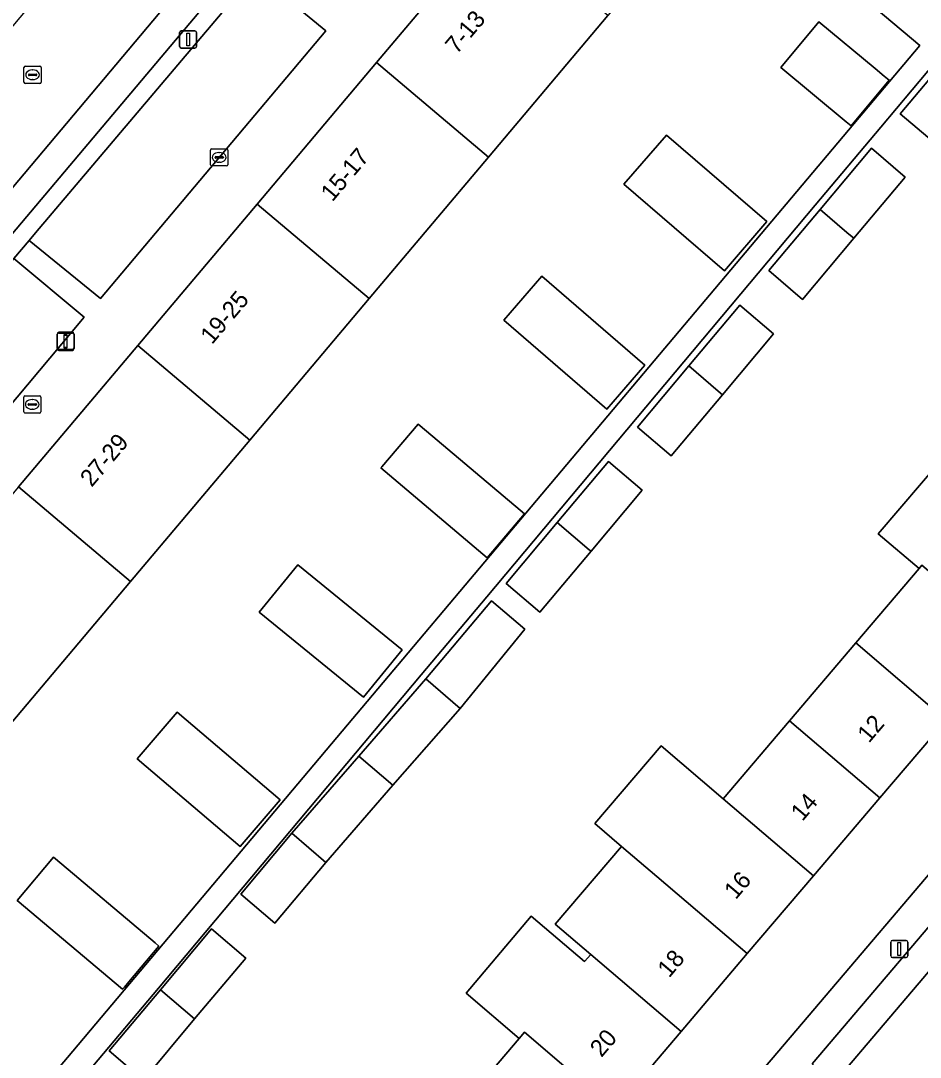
# Model space of a CAD drawing. Extents: x 162523 to 163266, y 381230 to 382050.
# Drawn here: x 163038.7 to 163090.9, y 381671.5 to 381731.7 of the extents above; entities that cross this region are included whole.
import ezdxf

# ---------------------------------------------------------------- set-up
doc = ezdxf.new("R2010")
doc.units = 0
for name, color, linetype in [('IMGEO_Brandkraan', 7, 'Continuous'), ('IMGEO_Erf', 7, 'Continuous'), ('IMGEO_Groenvoorziening', 7, 'Continuous'), ('IMGEO_Kolk', 7, 'Continuous'), ('IMGEO_Lichtmast', 7, 'Continuous'), ('IMGEO_Pand', 7, 'Continuous'), ('IMGEO_Pand_nummerreeks', 7, 'Continuous'), ('IMGEO_Parkeervlak_open', 7, 'Continuous'), ('IMGEO_Rijbaan_lokaal_open', 7, 'Continuous'), ('IMGEO_Rioolput', 7, 'Continuous'), ('IMGEO_Voetpad_open', 7, 'Continuous')]:
    doc.layers.add(name, color=color, linetype=linetype)

msp = doc.modelspace()

# ---------------------------------------------------------------- linework, layer by layer
at = {"layer": 'IMGEO_Brandkraan'}
for p, q in [((163038.839, 381709.011), (163038.839, 381709.863)), ((163038.914, 381709.937), (163039.766, 381709.937)), ((163039.84, 381709.863), (163039.84, 381709.011)), ((163039.098, 381709.431), (163039.098, 381709.443)), ((163039.536, 381709.394), (163039.138, 381709.394)), ((163039.141, 381709.48), (163039.539, 381709.48)), ((163039.327, 381709.717), (163039.352, 381709.717)), ((163039.582, 381709.443), (163039.582, 381709.431)), ((163039.766, 381708.937), (163038.914, 381708.937)), ((163039.35, 381709.157), (163039.325, 381709.157))]:
    msp.add_line(p, q, dxfattribs=at)
for points in [[(163038.839, 381709.011), (163038.839, 381709.863)], [(163038.914, 381709.937), (163039.766, 381709.937)], [(163039.84, 381709.863), (163039.84, 381709.011)], [(163039.766, 381708.937), (163038.914, 381708.937)]]:
    msp.add_lwpolyline(points, dxfattribs=at)
for centre, radius, start, end in [((163038.916, 381709.861), 0.0765, 91.55205, 178.44795), ((163038.916, 381709.861), 0.0765, 91.55205, 178.44795), ((163039.764, 381709.861), 0.0765, 1.55205, 88.44795), ((163039.764, 381709.861), 0.0765, 1.55205, 88.44795), ((163039.138, 381709.44), 0.0403, 85.87752, 175.75265), ((163039.135, 381709.43), 0.0366, 178.93798, 274.71019), ((163039.539, 381709.437), 0.043, 264.86636, 352.45326), ((163039.543, 381709.442), 0.0386, 1.73085, 96.63898), ((163038.916, 381709.013), 0.0765, 181.55205, 268.44795), ((163038.916, 381709.013), 0.0765, 181.55205, 268.44795), ((163039.764, 381709.013), 0.0765, 271.55205, 358.44795), ((163039.764, 381709.013), 0.0765, 271.55205, 358.44795)]:
    msp.add_arc(centre, radius, start, end, dxfattribs=at)
for centre, major_axis, ratio, start_param, end_param in [((163039.326, 381709.437), (-0.387, 0.002), 0.722429, 4.712389, 7.853982), ((163039.351, 381709.437), (-0.39, 0.002), 0.717154, 1.570796, 4.712389)]:
    msp.add_ellipse(centre, major_axis=major_axis, ratio=ratio, start_param=start_param, end_param=end_param, dxfattribs=at)
at = {"layer": 'IMGEO_Erf'}
for points in [[(163090.925, 381730.297), (163079.455, 381739.927), (163072.792, 381732.029), (163065.857, 381723.808), (163058.923, 381715.588), (163051.988, 381707.368), (163045.053, 381699.148), (163038.118, 381690.928), (163031.184, 381682.707), (163024.249, 381674.487), (163017.314, 381666.267), (163013.605, 381661.87), (163012.985, 381661.135), (163015.909, 381658.668), (163013.303, 381655.58), (163010.379, 381658.047)], [(163010.563, 381654.46), (163017.971, 381648.209), (163021.742, 381652.652), (163023.909, 381650.812), (163041.702, 381671.863), (163057.046, 381690.086), (163090.925, 381730.297)], [(163092.298, 381729.892), (163088.656, 381725.554), (163084.839, 381721.006), (163081.022, 381716.459), (163077.205, 381711.911), (163073.387, 381707.363), (163069.571, 381702.816), (163065.753, 381698.268), (163061.937, 381693.721), (163058.12, 381689.174), (163054.302, 381684.626), (163050.485, 381680.079), (163046.668, 381675.531), (163042.851, 381670.984)], [(163091.741, 381724.648), (163089.78, 381726.321), (163092.583, 381729.66)], [(163064.09, 381668.438), (163067.641, 381672.609), (163064.546, 381675.242), (163068.338, 381679.698), (163071.433, 381677.064), (163071.79, 381677.484), (163069.726, 381679.244), (163073.581, 381683.763), (163072.032, 381685.084), (163075.886, 381689.604), (163079.49, 381686.531), (163083.34, 381691.054), (163087.19, 381695.577), (163090.87, 381699.901), (163088.504, 381701.915), (163092.271, 381706.341)]]:
    msp.add_lwpolyline(points, dxfattribs=at)
for points in [[(163082.844, 381729.005), (163085.048, 381731.661), (163088.316, 381728.948), (163088.839, 381728.513), (163089.127, 381728.275), (163086.924, 381725.619), (163086.636, 381725.858)], [(163073.724, 381722.227), (163076.186, 381725.087), (163082.02, 381720.065), (163079.559, 381717.206)], [(163082.136, 381717.216), (163085.118, 381720.768), (163088.098, 381724.318), (163090.059, 381722.644), (163087.078, 381719.093), (163084.097, 381715.542)], [(163066.737, 381714.331), (163068.948, 381716.889), (163074.93, 381711.72), (163072.719, 381709.161)], [(163079.443, 381709.999), (163076.464, 381706.451), (163074.503, 381708.125), (163077.483, 381711.674), (163080.454, 381715.212), (163082.414, 381713.538)], [(163115.395, 381710.308), (163111.562, 381713.566), (163107.84, 381709.193), (163103.99, 381704.67), (163100.14, 381700.146), (163096.29, 381695.623), (163092.44, 381691.1), (163088.59, 381686.576), (163084.74, 381682.054), (163080.89, 381677.53), (163077.04, 381673.007), (163073.19, 381668.483), (163069.34, 381663.96), (163065.49, 381659.437), (163061.64, 381654.913), (163057.443, 381649.983), (163061.302, 381646.699), (163083.389, 381672.655)], [(163059.589, 381705.749), (163059.646, 381705.816), (163061.765, 381708.294), (163061.878, 381708.199), (163067.691, 381703.295), (163067.947, 381703.079), (163065.77, 381700.534)], [(163071.808, 381700.906), (163068.833, 381697.362), (163066.873, 381699.037), (163069.848, 381702.58), (163072.824, 381706.124), (163074.784, 381704.45)], [(163052.524, 381697.377), (163054.769, 381700.125), (163060.825, 381695.177), (163058.579, 381692.429)], [(163056.403, 381682.832), (163053.431, 381679.291), (163051.453, 381680.98), (163054.425, 381684.521), (163058.318, 381689.005), (163062.212, 381693.486), (163066.029, 381698.032), (163067.953, 381696.389), (163064.209, 381691.781), (163060.291, 381687.319)], [(163053.735, 381686.463), (163051.425, 381683.751), (163045.443, 381688.847), (163047.753, 381691.559)], [(163038.467, 381680.626), (163040.578, 381683.129), (163040.683, 381683.041), (163046.483, 381678.148), (163046.696, 381677.968), (163044.951, 381675.9), (163044.689, 381675.589), (163044.585, 381675.465)], [(163048.77, 381673.736), (163045.792, 381670.187), (163043.812, 381671.877), (163046.791, 381675.426), (163049.762, 381678.966), (163051.741, 381677.276)]]:
    msp.add_lwpolyline(points, close=True, dxfattribs=at)
at = {"layer": 'IMGEO_Groenvoorziening'}
for points in [[(163056.392, 381731.144), (163052.301, 381734.506), (163039.535, 381719.397), (163039.158, 381718.954), (163043.299, 381715.6)], [(163042.36, 381714.499), (163038.27, 381717.911), (163025.128, 381702.21), (163024.957, 381701.991), (163029.059, 381698.67), (163029.258, 381698.904)]]:
    msp.add_lwpolyline(points, close=True, dxfattribs=at)
at = {"layer": 'IMGEO_Kolk'}
for p, q in [((163049.775, 381724.29), (163050.627, 381724.29)), ((163049.7, 381723.364), (163049.7, 381724.216)), ((163049.959, 381723.784), (163049.959, 381723.796)), ((163050.397, 381723.747), (163049.999, 381723.747)), ((163050.002, 381723.833), (163050.4, 381723.833)), ((163050.188, 381724.07), (163050.213, 381724.07)), ((163050.443, 381723.796), (163050.443, 381723.784)), ((163050.701, 381724.216), (163050.701, 381723.364)), ((163050.627, 381723.29), (163049.775, 381723.29)), ((163050.211, 381723.51), (163050.186, 381723.51))]:
    msp.add_line(p, q, dxfattribs=at)
for points in [[(163049.775, 381724.29), (163050.627, 381724.29)], [(163049.7, 381723.364), (163049.7, 381724.216)], [(163050.701, 381724.216), (163050.701, 381723.364)], [(163050.627, 381723.29), (163049.775, 381723.29)]]:
    msp.add_lwpolyline(points, dxfattribs=at)
for centre, radius, start, end in [((163049.777, 381724.214), 0.0765, 91.55205, 178.44795), ((163049.777, 381724.214), 0.0765, 91.55205, 178.44795), ((163050.625, 381724.214), 0.0765, 1.55205, 88.44795), ((163050.625, 381724.214), 0.0765, 1.55205, 88.44795), ((163049.999, 381723.793), 0.0403, 85.87752, 175.75265), ((163049.996, 381723.783), 0.0366, 178.93798, 274.71019), ((163050.4, 381723.79), 0.043, 264.86636, 352.45326), ((163050.404, 381723.795), 0.0386, 1.73085, 96.63898), ((163049.777, 381723.366), 0.0765, 181.55205, 268.44795), ((163049.777, 381723.366), 0.0765, 181.55205, 268.44795), ((163050.625, 381723.366), 0.0765, 271.55205, 358.44795), ((163050.625, 381723.366), 0.0765, 271.55205, 358.44795)]:
    msp.add_arc(centre, radius, start, end, dxfattribs=at)
for centre, major_axis, ratio, start_param, end_param in [((163050.187, 381723.79), (-0.387, 0.002), 0.722429, 4.712389, 7.853982), ((163050.212, 381723.79), (-0.39, 0.002), 0.717154, 1.570796, 4.712389)]:
    msp.add_ellipse(centre, major_axis=major_axis, ratio=ratio, start_param=start_param, end_param=end_param, dxfattribs=at)
at = {"layer": 'IMGEO_Lichtmast'}
for p, q in [((163047.899, 381730.238), (163047.899, 381731.038)), ((163047.899, 381731.038), (163047.899, 381730.238)), ((163047.999, 381731.138), (163048.789, 381731.138)), ((163048.789, 381731.138), (163047.999, 381731.138)), ((163048.889, 381731.038), (163048.889, 381730.238)), ((163048.889, 381730.238), (163048.889, 381731.038)), ((163048.789, 381730.138), (163047.999, 381730.138)), ((163047.999, 381730.138), (163048.789, 381730.138)), ((163040.779, 381712.728), (163040.779, 381713.528)), ((163040.779, 381713.528), (163040.779, 381712.728)), ((163040.78, 381712.678), (163040.78, 381713.478)), ((163040.78, 381713.478), (163040.78, 381712.678)), ((163040.879, 381713.628), (163041.669, 381713.628)), ((163041.669, 381713.628), (163040.879, 381713.628)), ((163040.88, 381713.578), (163041.67, 381713.578)), ((163041.67, 381713.578), (163040.88, 381713.578)), ((163041.769, 381713.528), (163041.769, 381712.728)), ((163041.769, 381712.728), (163041.769, 381713.528)), ((163041.77, 381713.478), (163041.77, 381712.678)), ((163041.77, 381712.678), (163041.77, 381713.478)), ((163041.669, 381712.628), (163040.879, 381712.628)), ((163040.879, 381712.628), (163041.669, 381712.628)), ((163041.67, 381712.578), (163040.88, 381712.578)), ((163040.88, 381712.578), (163041.67, 381712.578)), ((163089.222, 381677.401), (163089.222, 381678.201)), ((163089.222, 381678.201), (163089.222, 381677.401)), ((163089.322, 381678.301), (163090.112, 381678.301)), ((163090.112, 381678.301), (163089.322, 381678.301)), ((163090.212, 381678.201), (163090.212, 381677.401)), ((163090.212, 381677.401), (163090.212, 381678.201)), ((163090.112, 381677.301), (163089.322, 381677.301)), ((163089.322, 381677.301), (163090.112, 381677.301))]:
    msp.add_line(p, q, dxfattribs=at)
for points in [[(163048.319, 381731.013), (163048.469, 381731.013), (163048.469, 381730.263), (163048.319, 381730.263), (163048.319, 381731.013)], [(163041.199, 381713.503), (163041.349, 381713.503), (163041.349, 381712.753), (163041.199, 381712.753), (163041.199, 381713.503)], [(163041.2, 381713.453), (163041.35, 381713.453), (163041.35, 381712.703), (163041.2, 381712.703), (163041.2, 381713.453)], [(163089.642, 381678.176), (163089.792, 381678.176), (163089.792, 381677.426), (163089.642, 381677.426), (163089.642, 381678.176)]]:
    msp.add_lwpolyline(points, dxfattribs=at)
for centre, start, end in [((163047.999, 381731.038), 90, 180), ((163047.999, 381731.038), 90, 180), ((163048.789, 381731.038), 0, 90), ((163048.789, 381731.038), 360, 90), ((163047.999, 381730.238), 180, 270), ((163047.999, 381730.238), 180, 270), ((163048.789, 381730.238), 270, 0), ((163048.789, 381730.238), 270, 0), ((163040.879, 381713.528), 90, 180), ((163040.879, 381713.528), 90, 180), ((163040.88, 381713.478), 90, 180), ((163040.88, 381713.478), 90, 180), ((163041.669, 381713.528), 0, 90), ((163041.669, 381713.528), 360, 90), ((163041.67, 381713.478), 0, 90), ((163041.67, 381713.478), 360, 90), ((163040.879, 381712.728), 180, 270), ((163040.879, 381712.728), 180, 270), ((163040.88, 381712.678), 180, 270), ((163040.88, 381712.678), 180, 270), ((163041.669, 381712.728), 270, 0), ((163041.669, 381712.728), 270, 0), ((163041.67, 381712.678), 270, 0), ((163041.67, 381712.678), 270, 0), ((163089.322, 381678.201), 90, 180), ((163089.322, 381678.201), 90, 180), ((163090.112, 381678.201), 0, 90), ((163090.112, 381678.201), 360, 90), ((163089.322, 381677.401), 180, 270), ((163089.322, 381677.401), 180, 270), ((163090.112, 381677.401), 270, 0), ((163090.112, 381677.401), 270, 0)]:
    msp.add_arc(centre, 0.1, start, end, dxfattribs=at)
at = {"layer": 'IMGEO_Pand'}
for points in [[(163066.281, 381737.522), (163059.346, 381729.301), (163065.857, 381723.808), (163072.792, 381732.029)], [(163082.844, 381729.005), (163086.636, 381725.858), (163086.924, 381725.619), (163089.127, 381728.275), (163088.839, 381728.513), (163088.316, 381728.948), (163085.048, 381731.661)], [(163094.584, 381728.034), (163094.03, 381728.484), (163092.583, 381729.66), (163089.78, 381726.321), (163091.741, 381724.648)], [(163058.923, 381715.588), (163065.857, 381723.808), (163059.346, 381729.301), (163052.411, 381721.081)], [(163082.02, 381720.065), (163076.186, 381725.087), (163073.724, 381722.227), (163079.559, 381717.206)], [(163085.118, 381720.768), (163086.678, 381719.435), (163087.078, 381719.093), (163090.059, 381722.644), (163088.098, 381724.318)], [(163058.923, 381715.588), (163052.411, 381721.081), (163045.477, 381712.861), (163051.988, 381707.368)], [(163087.078, 381719.093), (163086.678, 381719.435), (163085.118, 381720.768), (163082.136, 381717.216), (163084.097, 381715.542)], [(163074.93, 381711.72), (163068.948, 381716.889), (163066.737, 381714.331), (163072.719, 381709.161)], [(163077.483, 381711.674), (163079.188, 381710.217), (163079.443, 381709.999), (163082.414, 381713.538), (163080.454, 381715.212)], [(163045.053, 381699.148), (163051.988, 381707.368), (163045.477, 381712.861), (163038.542, 381704.641)], [(163079.443, 381709.999), (163079.188, 381710.217), (163077.483, 381711.674), (163074.503, 381708.125), (163076.464, 381706.451)], [(163059.589, 381705.749), (163065.77, 381700.534), (163067.947, 381703.079), (163067.691, 381703.295), (163061.878, 381708.199), (163061.765, 381708.294), (163059.646, 381705.816)], [(163094.89, 381704.624), (163094.637, 381704.327), (163092.271, 381706.341), (163088.504, 381701.915), (163090.87, 381699.901), (163091.04, 381700.101), (163096.29, 381695.623), (163100.14, 381700.146)], [(163069.848, 381702.58), (163071.699, 381700.999), (163071.808, 381700.906), (163074.784, 381704.45), (163072.824, 381706.124)], [(163045.053, 381699.148), (163038.542, 381704.641), (163031.607, 381696.42), (163038.118, 381690.928)], [(163071.808, 381700.906), (163071.699, 381700.999), (163069.848, 381702.58), (163066.873, 381699.037), (163068.833, 381697.362)], [(163060.825, 381695.177), (163054.769, 381700.125), (163052.524, 381697.377), (163058.579, 381692.429)], [(163091.04, 381700.101), (163090.87, 381699.901), (163087.19, 381695.577), (163092.44, 381691.1), (163096.29, 381695.623)], [(163067.953, 381696.389), (163066.029, 381698.032), (163062.212, 381693.486), (163064.209, 381691.781)], [(163088.59, 381686.576), (163092.44, 381691.1), (163087.19, 381695.577), (163083.34, 381691.054)], [(163064.209, 381691.781), (163062.212, 381693.486), (163058.318, 381689.005), (163060.291, 381687.319)], [(163053.735, 381686.463), (163047.753, 381691.559), (163045.443, 381688.847), (163051.425, 381683.751)], [(163088.59, 381686.576), (163083.34, 381691.054), (163079.49, 381686.531), (163084.74, 381682.054)], [(163079.49, 381686.531), (163075.886, 381689.604), (163072.032, 381685.084), (163073.581, 381683.763), (163075.64, 381682.007), (163080.89, 381677.53), (163084.74, 381682.054)], [(163060.291, 381687.319), (163058.318, 381689.005), (163054.425, 381684.521), (163056.403, 381682.832)], [(163056.403, 381682.832), (163054.425, 381684.521), (163051.453, 381680.98), (163053.431, 381679.291)], [(163075.64, 381682.007), (163073.581, 381683.763), (163069.726, 381679.244), (163071.79, 381677.484), (163077.04, 381673.007), (163080.89, 381677.53)], [(163038.467, 381680.626), (163044.585, 381675.465), (163044.689, 381675.589), (163044.951, 381675.9), (163046.696, 381677.968), (163046.483, 381678.148), (163040.683, 381683.041), (163040.578, 381683.129)], [(163071.79, 381677.484), (163071.433, 381677.064), (163068.338, 381679.698), (163064.546, 381675.242), (163067.641, 381672.609), (163067.94, 381672.961), (163073.19, 381668.483), (163077.04, 381673.007)], [(163046.791, 381675.426), (163048.77, 381673.736), (163051.741, 381677.276), (163049.762, 381678.966)], [(163048.77, 381673.736), (163046.791, 381675.426), (163043.812, 381671.877), (163045.792, 381670.187)], [(163067.94, 381672.961), (163067.641, 381672.609), (163064.09, 381668.438), (163069.34, 381663.96), (163073.19, 381668.483)]]:
    msp.add_lwpolyline(points, close=True, dxfattribs=at)
at = {"layer": 'IMGEO_Parkeervlak_open'}
msp.add_lwpolyline([(163056.818, 381741.488), (163055.527, 381742.589), (163052.803, 381739.418), (163018.166, 381698.234), (163019.445, 381697.16)], close=True, dxfattribs=at)
for points in [[(163079.904, 381662.933), (163094.918, 381680.596)], [(163091.825, 381679.552), (163084.667, 381671.131), (163085.398, 381670.406)]]:
    msp.add_lwpolyline(points, dxfattribs=at)
at = {"layer": 'IMGEO_Rijbaan_lokaal_open'}
msp.add_lwpolyline([(163050.901, 381746.533), (163013.536, 381702.12), (163018.166, 381698.234), (163052.803, 381739.418), (163055.527, 381742.589)], close=True, dxfattribs=at)
msp.add_lwpolyline([(163098.985, 381679.926), (163113.05, 381696.497), (163110.354, 381698.823), (163094.918, 381680.596), (163079.904, 381662.933), (163079.764, 381662.769), (163068.08, 381649.049), (163070.746, 381646.776), (163089.068, 381668.301), (163089.601, 381668.89)], dxfattribs=at)
at = {"layer": 'IMGEO_Rioolput'}
for p, q in [((163038.931, 381729.088), (163039.783, 381729.088)), ((163038.856, 381728.162), (163038.856, 381729.014)), ((163039.115, 381728.582), (163039.115, 381728.594)), ((163039.553, 381728.545), (163039.155, 381728.545)), ((163039.158, 381728.631), (163039.556, 381728.631)), ((163039.344, 381728.868), (163039.369, 381728.868)), ((163039.599, 381728.594), (163039.599, 381728.582)), ((163039.857, 381729.014), (163039.857, 381728.162)), ((163039.783, 381728.088), (163038.931, 381728.088)), ((163039.367, 381728.308), (163039.342, 381728.308))]:
    msp.add_line(p, q, dxfattribs=at)
for points in [[(163038.931, 381729.088), (163039.783, 381729.088)], [(163038.856, 381728.162), (163038.856, 381729.014)], [(163039.857, 381729.014), (163039.857, 381728.162)], [(163039.783, 381728.088), (163038.931, 381728.088)]]:
    msp.add_lwpolyline(points, dxfattribs=at)
for centre, radius, start, end in [((163038.933, 381729.012), 0.0765, 91.55205, 178.44795), ((163038.933, 381729.012), 0.0765, 91.55205, 178.44795), ((163039.781, 381729.012), 0.0765, 1.55205, 88.44795), ((163039.781, 381729.012), 0.0765, 1.55205, 88.44795), ((163039.155, 381728.591), 0.0403, 85.87752, 175.75265), ((163039.152, 381728.581), 0.0366, 178.93798, 274.71019), ((163039.556, 381728.588), 0.043, 264.86636, 352.45326), ((163039.56, 381728.593), 0.0386, 1.73085, 96.63898), ((163038.933, 381728.164), 0.0765, 181.55205, 268.44795), ((163038.933, 381728.164), 0.0765, 181.55205, 268.44795), ((163039.781, 381728.164), 0.0765, 271.55205, 358.44795), ((163039.781, 381728.164), 0.0765, 271.55205, 358.44795)]:
    msp.add_arc(centre, radius, start, end, dxfattribs=at)
for centre, major_axis, ratio, start_param, end_param in [((163039.343, 381728.588), (-0.387, 0.002), 0.722429, 4.712389, 7.853982), ((163039.368, 381728.588), (-0.39, 0.002), 0.717154, 1.570796, 4.712389)]:
    msp.add_ellipse(centre, major_axis=major_axis, ratio=ratio, start_param=start_param, end_param=end_param, dxfattribs=at)
at = {"layer": 'IMGEO_Voetpad_open'}
for points in [[(162997.814, 381670.044), (163009.861, 381684.126), (163010.916, 381685.315), (163011.199, 381685.63), (163023.867, 381700.625), (163024.957, 381701.991), (163025.128, 381702.21), (163038.27, 381717.911), (163039.158, 381718.954), (163039.535, 381719.397), (163052.301, 381734.506), (163053.336, 381735.62), (163053.524, 381735.843), (163065.334, 381750), (163066.206, 381751.02), (163067.464, 381752.514), (163067.838, 381752.947), (163067.046, 381753.62), (163063.994, 381750), (163058.655, 381743.667), (163056.818, 381741.488), (163019.445, 381697.16), (163017.576, 381694.943), (162999.919, 381674.1)], [(163099.35, 381726.253), (163074.342, 381747.088), (163073.214, 381745.74), (163077.036, 381742.517), (163079.725, 381740.247), (163079.455, 381739.927), (163090.925, 381730.297), (163057.046, 381690.086), (163041.702, 381671.863), (163023.909, 381650.812)], [(163038.542, 381704.641), (163045.477, 381712.861), (163052.411, 381721.081), (163059.346, 381729.301), (163066.281, 381737.522)], [(163052.301, 381734.506), (163056.392, 381731.144), (163043.299, 381715.6), (163039.158, 381718.954), (163038.27, 381717.911), (163042.36, 381714.499), (163029.258, 381698.904)], [(163042.851, 381670.984), (163046.668, 381675.531), (163050.485, 381680.079), (163054.302, 381684.626), (163058.12, 381689.174), (163061.937, 381693.721), (163065.753, 381698.268), (163069.571, 381702.816), (163073.387, 381707.363), (163077.205, 381711.911), (163081.022, 381716.459), (163084.839, 381721.006), (163088.656, 381725.554), (163092.298, 381729.892)], [(163130.519, 381728.076), (163122.861, 381719.099), (163118.851, 381714.364), (163116.554, 381711.671), (163115.395, 381710.308), (163083.389, 381672.655), (163061.302, 381646.699), (163059.389, 381644.452), (163043.741, 381626.048), (163046.532, 381623.783), (163047.165, 381624.502)], [(163085.398, 381670.406), (163084.667, 381671.131), (163091.825, 381679.552)]]:
    msp.add_lwpolyline(points, dxfattribs=at)

# ---------------------------------------------------------------- texts
at = {"layer": 'IMGEO_Pand_nummerreeks'}
for s, rotation, p in [('7-13', 49.84922, (163064.01, 381729.742)), ('15-17', 49.84794, (163056.778, 381721.17)), ('19-25', 49.84922, (163049.784, 381712.88)), ('27-29', 49.84794, (163042.791, 381704.59)), ('12', 49.59694, (163087.96, 381689.724)), ('14', 49.59694, (163084.09, 381685.176)), ('16', 49.59523, (163080.217, 381680.627)), ('18', 49.59523, (163076.347, 381676.081)), ('20', 49.59523, (163072.416, 381671.461))]:
    msp.add_text(s, height=1, rotation=rotation, dxfattribs=at).set_placement(p)

doc.saveas('drawing.dxf')
